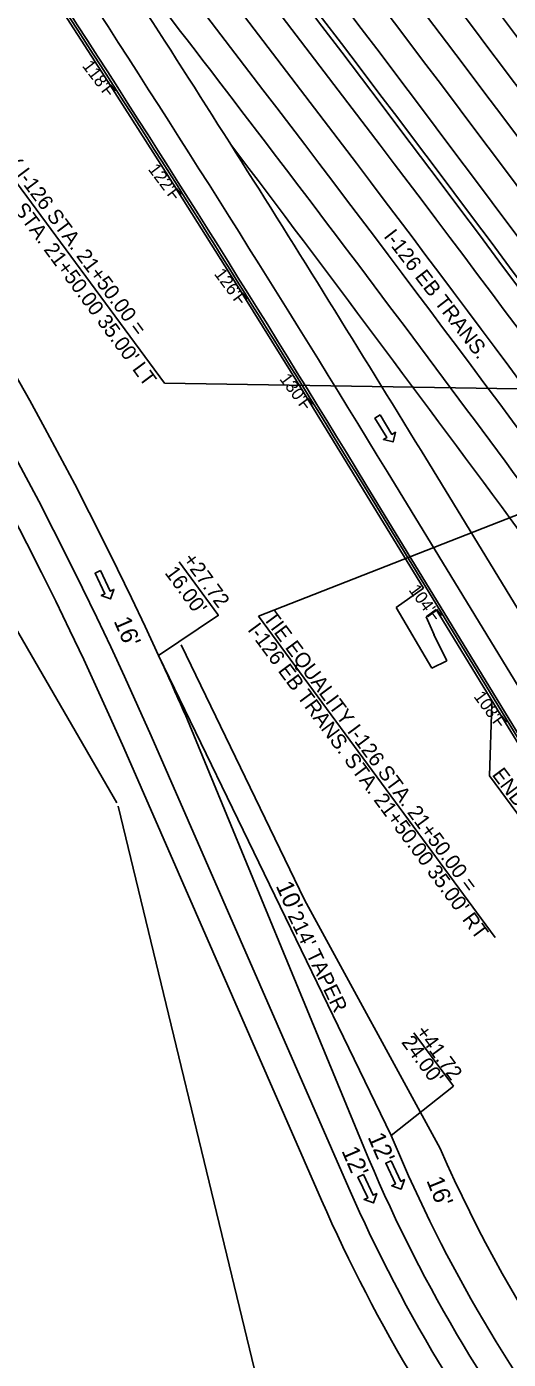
# Model space of a CAD drawing. Extents: x 1966090 to 1975830, y 788086 to 801233.
# Drawn here: x 1970241 to 1970435, y 796566 to 797102 of the extents above; entities that cross this region are included whole.
import ezdxf

# ---------------------------------------------------------------- set-up
doc = ezdxf.new("R2010")
doc.units = 0
for name, color, linetype in [('BR_PROPOSED_DRAINAGE', 7, 'Continuous'), ('BR_REBAR', 7, 'Continuous'), ('RD_EX_Driveway_txCode', 7, 'Continuous'), ('RD_EX_RW_TX', 7, 'Continuous'), ('RD_EX_SU_Gas', 7, 'Continuous'), ('RD_EX_TX_Dam_ELEV', 7, 'Continuous'), ('RD_PD_PaveShd', 7, 'Continuous'), ('RD_Sketch6', 7, 'Continuous'), ('RD_Sketch8', 7, 'Continuous'), ('RD_Sketch9', 7, 'Continuous')]:
    doc.layers.add(name, color=color, linetype=linetype)

msp = doc.modelspace()

# ---------------------------------------------------------------- linework, layer by layer
at = {"layer": 'BR_PROPOSED_DRAINAGE'}
for p, q in [((1970244.22, 797125.29), (1970271.25, 797083.51)), ((1970271.25, 797083.51), (1970298.03, 797041.58)), ((1970298.03, 797041.58), (1970324.57, 796999.49)), ((1970324.57, 796999.49), (1970350.85, 796957.26)), ((1970400.54, 796876.09), (1970350.85, 796957.26)), ((1970400.54, 796876.09), (1970389.56, 796868.27)), ((1970389.56, 796868.27), (1970403.94, 796843.94)), ((1970405.76, 796867.54), (1970401.64, 796864.61)), ((1970404.88, 796857.39), (1970401.64, 796864.61)), ((1970405.76, 796867.54), (1970428.93, 796829.58)), ((1970404.82, 796857.51), (1970409.95, 796846.82)), ((1970403.94, 796843.94), (1970409.95, 796846.82)), ((1970428.93, 796829.58), (1970481.23, 796743.9))]:
    msp.add_line(p, q, dxfattribs=at)
at = {"layer": 'BR_REBAR'}
for p, q in [((1970377.42, 796917.81), (1970485.02, 796741.53)), ((1970376.57, 796917.29), (1970484.16, 796741.01))]:
    msp.add_line(p, q, dxfattribs=at)
msp.add_arc((1963181.81, 792525.99), 8429, 31.397656, 33.871644, dxfattribs=at)
at = {"layer": 'RD_EX_Driveway_txCode'}
for points in [[(1970383.11, 796945.7), (1970381.06, 796944.45), (1970385.84, 796936.62), (1970384.45, 796935.77), (1970388.34, 796934.83), (1970389.28, 796938.72), (1970387.89, 796937.87)], [(1970270.71, 796883.14), (1970268.55, 796882.11), (1970272.47, 796873.82), (1970271, 796873.13), (1970274.76, 796871.78), (1970276.11, 796875.55), (1970274.64, 796874.85)], [(1970387.57, 796645.99), (1970385.4, 796644.96), (1970389.32, 796636.67), (1970387.85, 796635.97), (1970391.62, 796634.63), (1970392.96, 796638.39), (1970391.49, 796637.7)], [(1970376.42, 796640.4), (1970374.25, 796639.37), (1970378.18, 796631.08), (1970376.71, 796630.39), (1970380.47, 796629.04), (1970381.82, 796632.81), (1970380.35, 796632.11)]]:
    msp.add_lwpolyline(points, close=True, dxfattribs=at)
at = {"layer": 'RD_EX_SU_Gas'}
msp.add_line((1970376.6, 796651.49), (1970305.69, 796823.13), dxfattribs=at)
for centre, radius, start, end in [((1958843.44, 788350.87), 14500, 36.397656, 39.566224), ((1958843.44, 788350.87), 14488, 36.397656, 39.566224), ((1961201.85, 790089.49), 11512, 36.397656, 39.351802), ((1961201.85, 790089.49), 11500, 36.397656, 39.351802), ((1968885.76, 796201.61), 1550, 23.63926, 24.69023), ((1970931.23, 796880.36), 600, 202.42407, 234.38356)]:
    msp.add_arc(centre, radius, start, end, dxfattribs=at)
at = {"layer": 'RD_EX_TX_Dam_ELEV'}
for p, q in [((1970277.33, 796789.87), (1970203.01, 796917.79)), ((1970277.87, 796788.53), (1970332.59, 796562.06))]:
    msp.add_line(p, q, dxfattribs=at)
at = {"layer": 'RD_PD_PaveShd'}
for p, q in [((1970377.42, 796917.81), (1970485.02, 796741.53)), ((1970303.1, 796853.34), (1970352.74, 796750.86)), ((1970280.04, 796811.9), (1970359.59, 796630.15)), ((1970352.74, 796750.86), (1970407.29, 796650.86))]:
    msp.add_line(p, q, dxfattribs=at)
for centre, radius, start, end in [((1968885.76, 796201.61), 1522, 23.63926, 54.77615), ((1963181.81, 792525.99), 8430, 31.397656, 34.6698), ((1970931.23, 796880.36), 572, 203.6552, 226.0941), ((1970931.23, 796880.36), 624, 203.63926, 233.79058)]:
    msp.add_arc(centre, radius, start, end, dxfattribs=at)
at = {"layer": 'RD_Sketch6'}
for p, q in [((1970296.39, 796958.41), (1970200.01, 797089.15)), ((1970296.39, 796958.41), (1970514.75, 796954.97)), ((1970334.19, 796864.86), (1970458.41, 796913.43)), ((1970317.95, 796865.48), (1970302.33, 796886.68)), ((1970429.45, 796735.65), (1970334.19, 796864.86)), ((1970428.1, 796829.59), (1970427.09, 796800.73)), ((1970470.37, 796742.03), (1970427.09, 796800.73)), ((1970412.6, 796675.89), (1970396.7, 796697.45)), ((1970412.6, 796675.89), (1970387.55, 796656.07))]:
    msp.add_line(p, q, dxfattribs=at)
msp.add_lwpolyline([(1970317.95, 796865.48), (1970318.14, 796865.23), (1970294.05, 796849.07)], dxfattribs=at)
at = {"layer": 'RD_Sketch8'}
for p, q in [((1970399.62, 796931.35), (1970507.21, 796755.07)), ((1970385.96, 796923.02), (1970493.55, 796746.74)), ((1970294.05, 796849.07), (1970387.55, 796656.07)), ((1970291.03, 796816.71), (1970370.59, 796634.96)), ((1970387.55, 796656.07), (1970392.57, 796644.59))]:
    msp.add_line(p, q, dxfattribs=at)
for centre, radius, start, end in [((1958843.44, 788350.87), 14476, 36.397656, 39.566224), ((1968885.76, 796201.61), 1550, 24.69023, 54.77615), ((1968885.76, 796201.61), 1534, 23.63926, 54.77615), ((1961201.85, 790089.49), 11524, 36.397656, 39.351802), ((1963181.81, 792525.99), 8440, 31.397656, 34.6724), ((1963181.81, 792525.99), 8456, 31.397656, 33.311565), ((1961201.85, 790089.49), 11488, 36.397656, 38.049017), ((1958843.44, 788350.87), 14524, 36.397656, 37.323179), ((1958843.44, 788350.87), 14512, 36.397656, 37.215454), ((1958787.09, 788309.34), 14476, 36.397503, 37.164449), ((1970931.23, 796880.36), 588, 203.63926, 234.98689), ((1970931.23, 796880.36), 612, 203.63926, 234.98689)]:
    msp.add_arc(centre, radius, start, end, dxfattribs=at)
at = {"layer": 'RD_Sketch9'}
for centre, radius, end in [((1958787.09, 788309.34), 14534, 39.713887), ((1958843.44, 788350.87), 14466, 39.566224)]:
    msp.add_arc(centre, radius, 36.397656, end, dxfattribs=at)

# ---------------------------------------------------------------- texts
at = {"layer": 'RD_EX_Driveway_txCode'}
for s, rotation, p in [("16'", 293.42, (1970275.91, 796862.91)), ("10'", 294.0609, (1970341.07, 796756.5)), ("12'", 293.42, (1970378.03, 796655.54)), ("12'", 293.42, (1970367.52, 796649.99)), ("16'", 292.0421, (1970401.67, 796638.07))]:
    msp.add_text(s, height=7, rotation=rotation, dxfattribs=at).set_placement(p)
at = {"layer": 'RD_EX_RW_TX'}
for s, rotation, p in [("118'F", 307.3855, (1970263.14, 797085.89)), ("122'F", 307.1879, (1970289.64, 797044.37)), ("126'F", 306.9904, (1970316.19, 797002.31)), ("130'F", 306.7928, (1970342.48, 796960.1)), ("104'F", 306.3977, (1970394.43, 796875.33)), ("108'F", 306.3977, (1970420.58, 796832.49))]:
    msp.add_text(s, height=5, rotation=rotation, dxfattribs=at).set_placement(p)
at = {"layer": 'RD_Sketch6'}
for s, height, rotation, p in [('TIE EQUALITY I-126 STA. 21+50.00 =', 5.9996, 306.5592, (1970202.83, 797087.67)), ("I-126 WB TRANS. STA. 21+50.00 35.00' LT", 5.9996, 306.5592, (1970195.6, 797082.31)), ('I-126 EB TRANS.', 5.9996, 307.588, (1970384.34, 797017.43)), ('+27.72', 6, 306.3977, (1970303.54, 796887.57)), ("16.00'", 6, 306.3977, (1970296.3, 796882.23)), ('TIE EQUALITY I-126 STA. 21+50.00 =', 5.9996, 306.5592, (1970335.93, 796864.04)), ("I-126 EB TRANS. STA. 21+50.00 35.00' RT", 5.9996, 306.5592, (1970329.61, 796859.35)), ('END CRASH WALL', 5.9996, 306.5574, (1970427.89, 796801.11)), ("214' TAPER", 6, 295.7292, (1970345.86, 796744.51)), ('+41.72', 6, 306.3977, (1970397.11, 796697.74)), ("24.00'", 6, 306.3977, (1970391.47, 796693.59))]:
    msp.add_text(s, height=height, rotation=rotation, dxfattribs=at).set_placement(p)

doc.saveas('drawing.dxf')
